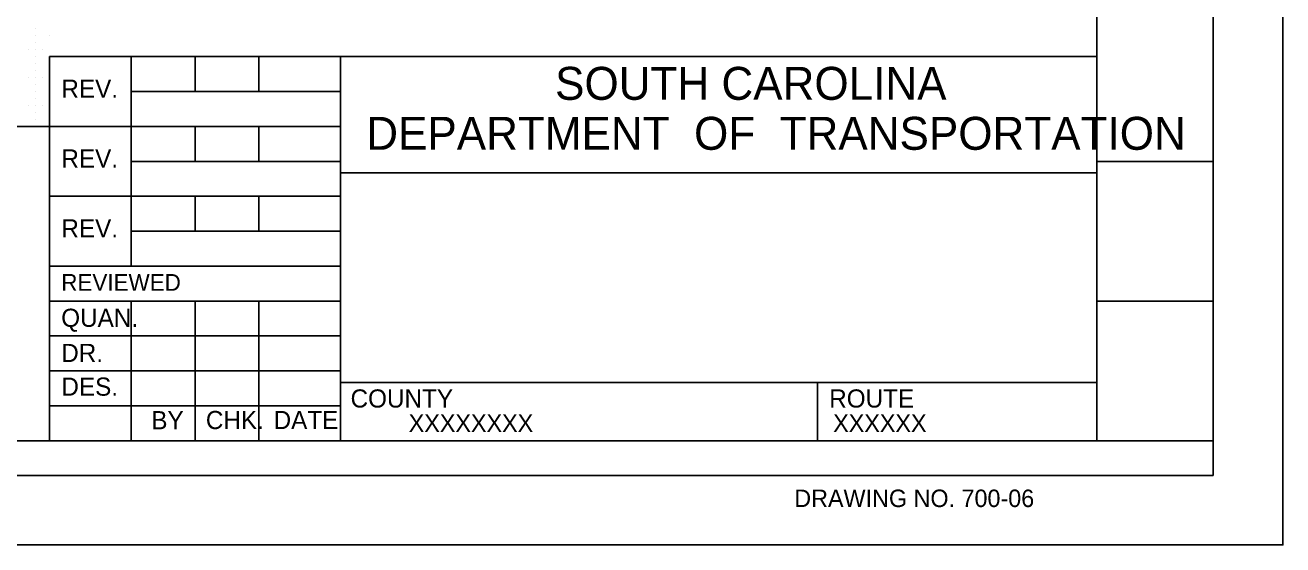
# Model space of a CAD drawing. Extents: x -0.04 to 4.87, y 0 to 1.83.
# Drawn here: x 2.214 to 2.964, y 0 to 0.31 of the extents above; entities that cross this region are included whole.
import ezdxf

# ---------------------------------------------------------------- set-up
doc = ezdxf.new("R2010")
doc.units = 0
for name, color, linetype in [('BR_BORDER LINES', 7, 'Continuous'), ('BR_GRID DOTS', 7, 'Continuous'), ('BR_GRID LINES', 7, 'Continuous'), ('BR_TEXT', 7, 'Continuous'), ('RD_SHT_IplotShp', 7, 'Continuous')]:
    doc.layers.add(name, color=color, linetype=linetype)

msp = doc.modelspace()

# ---------------------------------------------------------------- linework, layer by layer
at = {"layer": 'BR_BORDER LINES'}
for p, q in [((2.92272, 0.04127), (2.92272, 1.79153)), ((2.85328, 0.89543), (2.85328, 0.29544)), ((2.85328, 0.29544), (2.85328, 0.09683)), ((2.22828, 0.0621), (2.22828, 0.29127)), ((2.22828, 0.29127), (2.85328, 0.29127)), ((2.27689, 0.29127), (2.27689, 0.16627)), ((2.31509, 0.27044), (2.31509, 0.29127)), ((2.35328, 0.27044), (2.35328, 0.29127)), ((2.40189, 0.0621), (2.40189, 0.29127)), ((2.27689, 0.27044), (2.40189, 0.27044)), ((2.03557, 0.2496), (2.22828, 0.2496)), ((2.22828, 0.2496), (2.40189, 0.2496)), ((2.31509, 0.22877), (2.31509, 0.2496)), ((2.35328, 0.22877), (2.35328, 0.2496)), ((2.27689, 0.22877), (2.40189, 0.22877)), ((2.40189, 0.22183), (2.85328, 0.22183)), ((2.40189, 0.22183), (2.40189, 0.22183)), ((2.85328, 0.22183), (2.85328, 0.22183)), ((2.22828, 0.20794), (2.40189, 0.20794)), ((2.31509, 0.1871), (2.31509, 0.20794)), ((2.35328, 0.1871), (2.35328, 0.20794)), ((2.27689, 0.1871), (2.40189, 0.1871)), ((2.22828, 0.16627), (2.40189, 0.16627)), ((2.22828, 0.14544), (2.40189, 0.14544)), ((2.27689, 0.14544), (2.27689, 0.0621)), ((2.31509, 0.14544), (2.31509, 0.0621)), ((2.35328, 0.14544), (2.35328, 0.0621)), ((2.22828, 0.1246), (2.40189, 0.1246)), ((2.22828, 0.10377), (2.40189, 0.10377)), ((2.40189, 0.09683), (2.85328, 0.09683)), ((2.68662, 0.0621), (2.68662, 0.09683)), ((2.85328, 0.0621), (2.85328, 0.09683)), ((2.22828, 0.08294), (2.40189, 0.08294)), ((0.18664, 0.0621), (2.22829, 0.0621)), ((2.85328, 0.0621), (2.22829, 0.0621)), ((0.1172, 0.04127), (2.92272, 0.04127)), ((-0.03561, 0), (2.96439, 0))]:
    msp.add_line(p, q, dxfattribs=at)
at = {"layer": 'BR_GRID DOTS'}
for p, q in [((2.21996, 0.30794), (2.21996, 0.30794)), ((2.21996, 0.30377), (2.21996, 0.30377)), ((2.22829, 0.30377), (2.22829, 0.30377)), ((2.21579, 0.29544), (2.21579, 0.29544)), ((2.21996, 0.2996), (2.21996, 0.2996)), ((2.21996, 0.2996), (2.21996, 0.2996)), ((2.21996, 0.29544), (2.21996, 0.29544)), ((2.22412, 0.29544), (2.22412, 0.29544)), ((2.21996, 0.29127), (2.21996, 0.29127)), ((2.21996, 0.2871), (2.21996, 0.2871)), ((2.21579, 0.27877), (2.21579, 0.27877)), ((2.21996, 0.28294), (2.21996, 0.28294)), ((2.21996, 0.27877), (2.21996, 0.27877)), ((2.22412, 0.27877), (2.22412, 0.27877)), ((2.21996, 0.2746), (2.21996, 0.2746)), ((2.21996, 0.27044), (2.21996, 0.27044)), ((2.21996, 0.26627), (2.21996, 0.26627)), ((2.21579, 0.2621), (2.21579, 0.2621)), ((2.21996, 0.2621), (2.21996, 0.2621)), ((2.21996, 0.25794), (2.21996, 0.25794)), ((2.22412, 0.2621), (2.22412, 0.2621)), ((2.21996, 0.25377), (2.21996, 0.25377))]:
    msp.add_line(p, q, dxfattribs=at)
at = {"layer": 'BR_GRID LINES'}
for p, q in [((2.85328, 0.22877), (2.92272, 0.22877)), ((2.85328, 0.14544), (2.92272, 0.14544)), ((2.85328, 0.0621), (2.92272, 0.0621))]:
    msp.add_line(p, q, dxfattribs=at)
at = {"layer": 'RD_SHT_IplotShp'}
msp.add_lwpolyline([(-0.03561, 0), (2.96439, 0), (2.96439, 1.83333), (-0.03561, 1.83333)], close=True, dxfattribs=at)

# ---------------------------------------------------------------- texts
at = {"layer": 'BR_TEXT'}
for s, height, p in [('SOUTH CAROLINA', 0.0196543, (2.53001, 0.26548)), ('REV.', 0.010833, (2.23534, 0.26672)), ('DEPARTMENT  OF  TRANSPORTATION', 0.0196543, (2.41729, 0.23567)), ('REV.', 0.010833, (2.23534, 0.22506)), ('REV.', 0.010833, (2.23534, 0.18339)), ('REVIEWED', 0.01, (2.23528, 0.15156)), ('QUAN.', 0.010833, (2.23523, 0.13003)), ('DR.', 0.010833, (2.23525, 0.10907)), ('DES.', 0.010833, (2.23534, 0.08897)), ('COUNTY', 0.010833, (2.40794, 0.0819)), ('ROUTE', 0.010833, (2.69362, 0.0819)), ('BY', 0.010833, (2.289, 0.06894)), ('CHK.', 0.010833, (2.32157, 0.06905)), ('DATE', 0.010833, (2.36201, 0.06906)), ('XXXXXXXX       ', 0.0104167, (2.44263, 0.06736)), ('XXXXXX       ', 0.0104167, (2.69599, 0.06736)), ('DRAWING NO. 700-06', 0.0104167, (2.67278, 0.02254))]:
    msp.add_text(s, height=height, dxfattribs=at).set_placement(p)

doc.saveas('drawing.dxf')
